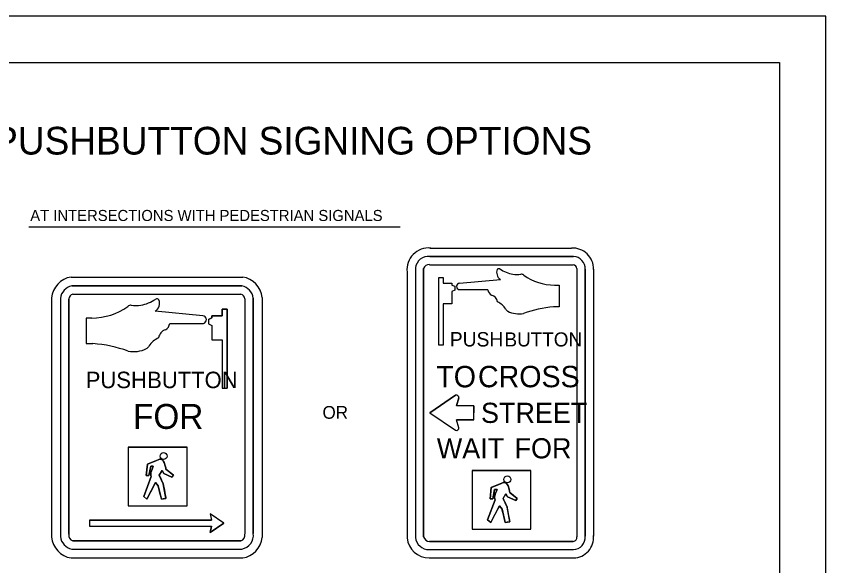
# Model space of a CAD drawing. Extents: x 1896459 to 1901611, y 1616229 to 1617416.
# Drawn here: x 1897720.6 to 1898159.1, y 1617118.8 to 1617416.5 of the extents above; entities that cross this region are included whole.
import ezdxf

# ---------------------------------------------------------------- set-up
doc = ezdxf.new("R2010")
doc.units = 0
for name, color, linetype in [('Level 24', 7, 'Continuous'), ('Level 8', 7, 'Continuous'), ('ROW_PR_Notes', 7, 'Continuous'), ('Sheets_General Details', 7, 'Continuous'), ('Signals_EX_Above Ground', 7, 'Continuous')]:
    doc.layers.add(name, color=color, linetype=linetype)

msp = doc.modelspace()

# ---------------------------------------------------------------- linework, layer by layer
at = {"layer": 'ROW_PR_Notes'}
for p, q in [((1897944.68, 1617290.9), (1898021.37, 1617290.9)), ((1897944.68, 1617286.4), (1898022.49, 1617286.4)), ((1898022.49, 1617286.4), (1897944.68, 1617286.4)), ((1897944.42, 1617281.9), (1898022.28, 1617281.9)), ((1897944.42, 1617281.9), (1898022.28, 1617281.9)), ((1897932.28, 1617277.93), (1897932.28, 1617133.9)), ((1897936.78, 1617280.12), (1897936.78, 1617134.18)), ((1897936.78, 1617280.12), (1897936.78, 1617134.18)), ((1897941.28, 1617279.75), (1897941.28, 1617134.56)), ((1897941.28, 1617134.56), (1897941.28, 1617279.75)), ((1898024.28, 1617279.75), (1898024.28, 1617134.56)), ((1898024.28, 1617279.75), (1898024.28, 1617134.56)), ((1898028.78, 1617279.44), (1898028.78, 1617134.79)), ((1898028.78, 1617134.79), (1898028.78, 1617279.44)), ((1898033.28, 1617279.38), (1898033.28, 1617134.79)), ((1897750.33, 1617275.2), (1897843.27, 1617275.2)), ((1897949.54, 1617238.3), (1897949.54, 1617274.9)), ((1897949.54, 1617274.9), (1897951.82, 1617274.9)), ((1897951.82, 1617274.9), (1897951.82, 1617271.91)), ((1897960.73, 1617271.92), (1897982.87, 1617273.96)), ((1897750.74, 1617270.4), (1897842.86, 1617270.4)), ((1897842.86, 1617270.4), (1897750.74, 1617270.4)), ((1897956.62, 1617270.87), (1897958.18, 1617270.2)), ((1897958.18, 1617268.13), (1897956.62, 1617267.45)), ((1897958.18, 1617270.2), (1897958.18, 1617268.13)), ((1897976.08, 1617268.35), (1897960.49, 1617268.35)), ((1898012.17, 1617270.77), (1898014.72, 1617270.77)), ((1897739.77, 1617263.87), (1897739.77, 1617134.41)), ((1897744.58, 1617263.65), (1897744.58, 1617134.63)), ((1897744.58, 1617263.65), (1897744.58, 1617134.63)), ((1897749.08, 1617263.37), (1897749.08, 1617135.94)), ((1897749.08, 1617135.94), (1897749.08, 1617263.37)), ((1897751.28, 1617265.9), (1897842.33, 1617265.9)), ((1897751.28, 1617265.9), (1897842.33, 1617265.9)), ((1897844.5, 1617263.48), (1897844.5, 1617136.05)), ((1897844.5, 1617263.48), (1897844.5, 1617136.05)), ((1897849, 1617263.83), (1897849, 1617136.4)), ((1897849, 1617136.4), (1897849, 1617263.83)), ((1897853.81, 1617264.1), (1897853.81, 1617134.18)), ((1897956.62, 1617267.45), (1897956.62, 1617260.76)), ((1897956.62, 1617260.76), (1897951.82, 1617260.76)), ((1897951.82, 1617260.76), (1897951.82, 1617238.3)), ((1897821.73, 1617254.26), (1897795.84, 1617256.64)), ((1897821.73, 1617254.26), (1897795.84, 1617256.64)), ((1897832.15, 1617254.25), (1897832.15, 1617257.75)), ((1897832.15, 1617257.75), (1897834.81, 1617257.75)), ((1897834.81, 1617257.75), (1897832.15, 1617257.75)), ((1897832.15, 1617257.75), (1897832.15, 1617254.25)), ((1897834.81, 1617257.75), (1897834.81, 1617214.95)), ((1897834.81, 1617214.95), (1897834.81, 1617257.75)), ((1897761.58, 1617252.92), (1897758.59, 1617252.92)), ((1897761.58, 1617252.92), (1897758.59, 1617252.92)), ((1897824.71, 1617252.24), (1897826.53, 1617253.04)), ((1897826.53, 1617253.04), (1897824.71, 1617252.24)), ((1897824.71, 1617252.24), (1897824.71, 1617249.82)), ((1897824.71, 1617252.24), (1897824.71, 1617249.82)), ((1897803.78, 1617250.09), (1897822.01, 1617250.09)), ((1897803.78, 1617250.09), (1897822.01, 1617250.09)), ((1897824.71, 1617249.82), (1897826.53, 1617249.03)), ((1897824.71, 1617249.82), (1897826.53, 1617249.03)), ((1897826.53, 1617249.03), (1897826.53, 1617241.21)), ((1897826.53, 1617249.03), (1897826.53, 1617241.21)), ((1897826.53, 1617241.21), (1897832.15, 1617241.21)), ((1897826.53, 1617241.21), (1897832.15, 1617241.21)), ((1897832.15, 1617241.21), (1897832.15, 1617214.95)), ((1897832.15, 1617241.21), (1897832.15, 1617214.95)), ((1897951.82, 1617238.3), (1897949.54, 1617238.3)), ((1897832.15, 1617214.95), (1897834.81, 1617214.95)), ((1897832.15, 1617214.95), (1897834.81, 1617214.95)), ((1897944.6, 1617201.67), (1897958.52, 1617211.15)), ((1897958.52, 1617211.15), (1897944.6, 1617201.67)), ((1897960.41, 1617209.73), (1897959.04, 1617205.42)), ((1897959.04, 1617205.42), (1897960.41, 1617209.73)), ((1897968.46, 1617205.42), (1897959.04, 1617205.42)), ((1897968.46, 1617205.42), (1897959.04, 1617205.42)), ((1897968.46, 1617205.42), (1897968.46, 1617201.67)), ((1897968.46, 1617201.67), (1897968.46, 1617205.42)), ((1897944.6, 1617201.67), (1897958.52, 1617192.2)), ((1897944.6, 1617201.67), (1897958.52, 1617192.2)), ((1897960.41, 1617193.62), (1897959.04, 1617197.93)), ((1897968.46, 1617197.93), (1897959.04, 1617197.93)), ((1897960.41, 1617193.62), (1897959.04, 1617197.93)), ((1897959.04, 1617197.93), (1897968.46, 1617197.93)), ((1897968.46, 1617197.93), (1897968.46, 1617201.67)), ((1897968.46, 1617197.93), (1897968.46, 1617201.67)), ((1897781.34, 1617183.1), (1897813.16, 1617183.1)), ((1897813.16, 1617183.1), (1897781.34, 1617183.1)), ((1897797.43, 1617176.23), (1897798.21, 1617176.52)), ((1897791.05, 1617167.65), (1897791.66, 1617173.86)), ((1897801.15, 1617173.51), (1897801.34, 1617172.92)), ((1897801.34, 1617172.92), (1897801.6, 1617171.89)), ((1897801.6, 1617171.89), (1897801.73, 1617171.09)), ((1897789.66, 1617156.41), (1897793.72, 1617167.13)), ((1897792.5, 1617167.78), (1897791.05, 1617167.65)), ((1897793.45, 1617168.62), (1897793.57, 1617169.3)), ((1897793.57, 1617169.3), (1897793.84, 1617170.24)), ((1897793.72, 1617167.13), (1897793.57, 1617167.6)), ((1897800.57, 1617168.78), (1897799.6, 1617170.52)), ((1897804.96, 1617166.9), (1897800.57, 1617168.78)), ((1897805.75, 1617167.97), (1897804.96, 1617166.9)), ((1897967.54, 1617170.46), (1897999.36, 1617170.46)), ((1897999.36, 1617170.46), (1897967.54, 1617170.46)), ((1897983.63, 1617163.59), (1897984.41, 1617163.88)), ((1897798.29, 1617158.98), (1897797.53, 1617162.19)), ((1897977.25, 1617155.01), (1897977.86, 1617161.22)), ((1897987.35, 1617160.87), (1897987.54, 1617160.28)), ((1897987.54, 1617160.28), (1897987.8, 1617159.25)), ((1897987.8, 1617159.25), (1897987.94, 1617158.45)), ((1897791.41, 1617154.87), (1897789.66, 1617156.41)), ((1897975.86, 1617143.77), (1897979.92, 1617154.49)), ((1897978.7, 1617155.14), (1897977.25, 1617155.01)), ((1897979.65, 1617155.98), (1897979.77, 1617156.66)), ((1897979.77, 1617156.66), (1897980.04, 1617157.59)), ((1897979.92, 1617154.49), (1897979.77, 1617154.96)), ((1897986.77, 1617156.14), (1897985.8, 1617157.88)), ((1897991.16, 1617154.25), (1897986.77, 1617156.14)), ((1897991.95, 1617155.32), (1897991.16, 1617154.25)), ((1897984.49, 1617146.34), (1897983.73, 1617149.54)), ((1897833.06, 1617141.9), (1897825.58, 1617146.98)), ((1897825.58, 1617146.98), (1897826.46, 1617143.54)), ((1897833.06, 1617141.9), (1897825.58, 1617146.98)), ((1897825.58, 1617146.98), (1897826.46, 1617143.54)), ((1897760.33, 1617143.54), (1897760.33, 1617140.26)), ((1897760.33, 1617143.54), (1897826.46, 1617143.54)), ((1897826.46, 1617143.54), (1897760.33, 1617143.54)), ((1897760.33, 1617143.54), (1897760.33, 1617140.26)), ((1897833.06, 1617141.9), (1897825.58, 1617136.82)), ((1897825.58, 1617136.82), (1897833.06, 1617141.9)), ((1897977.61, 1617142.23), (1897975.86, 1617143.77)), ((1897760.33, 1617140.26), (1897826.46, 1617140.26)), ((1897760.33, 1617140.26), (1897826.46, 1617140.26)), ((1897825.58, 1617136.82), (1897826.46, 1617140.26)), ((1897826.46, 1617140.26), (1897825.58, 1617136.82)), ((1897751.28, 1617132.38), (1897842.33, 1617132.38)), ((1897842.33, 1617132.38), (1897751.28, 1617132.38)), ((1897944.42, 1617132.07), (1898022.28, 1617132.07)), ((1898022.28, 1617132.07), (1897944.42, 1617132.07)), ((1897750.74, 1617127.88), (1897842.86, 1617127.88)), ((1897750.74, 1617127.88), (1897842.86, 1617127.88)), ((1897944.28, 1617127.57), (1898022.4, 1617127.57)), ((1897944.28, 1617127.57), (1898022.4, 1617127.57)), ((1897750.33, 1617123.07), (1897843.27, 1617123.07)), ((1897944.26, 1617123.07), (1898022.49, 1617123.07))]:
    msp.add_line(p, q, dxfattribs=at)
for points in [[(1897951.82, 1617271.91), (1897956.62, 1617271.91), (1897956.62, 1617270.87)], [(1898014.72, 1617270.77), (1898014.72, 1617259.02), (1898011.65, 1617259.02)], [(1897758.59, 1617252.92), (1897758.59, 1617239.17), (1897762.19, 1617239.17)], [(1897758.59, 1617252.92), (1897758.59, 1617239.17), (1897762.19, 1617239.17)], [(1897826.53, 1617253.04), (1897826.53, 1617254.25), (1897832.15, 1617254.25)], [(1897832.15, 1617254.25), (1897826.53, 1617254.25), (1897826.53, 1617253.04)], [(1897781.34, 1617183.1), (1897781.34, 1617151.28), (1897813.16, 1617151.28), (1897813.16, 1617183.1)], [(1897781.34, 1617183.1), (1897781.34, 1617151.28), (1897813.16, 1617151.28), (1897813.16, 1617183.1)], [(1897791.66, 1617173.86), (1897794.33, 1617174.96), (1897797.43, 1617176.23)], [(1897798.21, 1617176.52), (1897798.95, 1617176.53), (1897799.35, 1617176.43)], [(1897799.35, 1617176.43), (1897799.71, 1617176.23), (1897799.98, 1617175.96), (1897800.45, 1617175.35), (1897800.78, 1617174.7), (1897800.97, 1617174.15), (1897801.15, 1617173.51)], [(1897793.84, 1617170.24), (1897794.2, 1617171.22), (1897794.63, 1617172.18), (1897794.88, 1617172.76), (1897793.51, 1617172.74), (1897793.17, 1617171.09), (1897793.03, 1617170.37)], [(1897793.03, 1617170.37), (1897792.78, 1617169.12), (1897792.5, 1617167.78)], [(1897793.57, 1617167.6), (1897793.47, 1617168.24), (1897793.45, 1617168.62)], [(1897799.6, 1617170.52), (1897798.86, 1617169.27), (1897798.06, 1617167.9), (1897798.47, 1617167.03), (1897799.32, 1617165.21), (1897800.23, 1617163.26)], [(1897801.73, 1617171.09), (1897803.04, 1617170.07), (1897805.75, 1617167.97)], [(1897967.54, 1617170.46), (1897967.54, 1617138.64), (1897999.36, 1617138.64), (1897999.36, 1617170.46)], [(1897967.54, 1617170.46), (1897967.54, 1617138.64), (1897999.36, 1617138.64), (1897999.36, 1617170.46)], [(1897797.53, 1617162.19), (1897796.12, 1617163.94), (1897795.15, 1617162.05), (1897791.62, 1617155.22), (1897791.41, 1617154.87)], [(1897800.23, 1617163.26), (1897800.27, 1617163.09), (1897800.29, 1617162.96)], [(1897800.29, 1617162.96), (1897800.34, 1617162.66), (1897800.47, 1617161.99)], [(1897977.86, 1617161.22), (1897980.53, 1617162.32), (1897983.63, 1617163.59)], [(1897984.41, 1617163.88), (1897985.15, 1617163.89), (1897985.55, 1617163.79)], [(1897985.55, 1617163.79), (1897985.91, 1617163.59), (1897986.18, 1617163.32), (1897986.65, 1617162.71), (1897986.98, 1617162.06), (1897987.17, 1617161.51), (1897987.35, 1617160.87)], [(1897800.47, 1617161.99), (1897800.48, 1617161.92), (1897800.68, 1617160.88), (1897801.07, 1617158.78), (1897801.37, 1617157.19), (1897801.59, 1617156.06), (1897801.7, 1617155.35), (1897800.28, 1617155.05), (1897799.26, 1617154.87), (1897798.86, 1617156.51), (1897798.48, 1617158.13), (1897798.29, 1617158.98)], [(1897980.04, 1617157.59), (1897980.4, 1617158.58), (1897980.83, 1617159.54), (1897981.09, 1617160.12), (1897979.72, 1617160.1), (1897979.38, 1617158.44), (1897979.23, 1617157.73)], [(1897987.94, 1617158.45), (1897989.24, 1617157.43), (1897991.95, 1617155.32)], [(1897979.23, 1617157.73), (1897978.98, 1617156.47), (1897978.7, 1617155.14)], [(1897979.77, 1617154.96), (1897979.67, 1617155.59), (1897979.65, 1617155.98)], [(1897985.8, 1617157.88), (1897985.07, 1617156.63), (1897984.26, 1617155.26), (1897984.67, 1617154.39), (1897985.52, 1617152.57), (1897986.43, 1617150.61)], [(1897983.73, 1617149.54), (1897982.32, 1617151.3), (1897981.36, 1617149.41), (1897977.82, 1617142.58), (1897977.61, 1617142.23)], [(1897986.43, 1617150.61), (1897986.47, 1617150.45), (1897986.49, 1617150.32)], [(1897986.49, 1617150.32), (1897986.54, 1617150.01), (1897986.67, 1617149.35)], [(1897986.67, 1617149.35), (1897986.68, 1617149.28), (1897986.89, 1617148.24), (1897987.27, 1617146.14), (1897987.57, 1617144.55), (1897987.79, 1617143.41), (1897987.9, 1617142.71), (1897986.48, 1617142.41), (1897985.47, 1617142.23), (1897985.06, 1617143.87), (1897984.68, 1617145.49), (1897984.49, 1617146.34)]]:
    msp.add_lwpolyline(points, dxfattribs=at)
for points in [[(1897791.05, 1617167.65), (1897792.5, 1617167.78), (1897793.51, 1617172.74), (1897794.88, 1617172.76), (1897794.2, 1617171.22), (1897793.84, 1617170.24), (1897793.57, 1617169.3), (1897793.45, 1617168.62), (1897793.57, 1617167.6), (1897793.72, 1617167.13), (1897789.66, 1617156.41), (1897791.41, 1617154.87), (1897796.12, 1617163.94), (1897797.53, 1617162.19), (1897799.26, 1617154.87), (1897801.7, 1617155.35), (1897800.23, 1617163.26), (1897798.06, 1617167.9), (1897799.6, 1617170.52), (1897800.57, 1617168.78), (1897804.96, 1617166.9), (1897805.75, 1617167.97), (1897801.73, 1617171.09), (1897801.6, 1617171.89), (1897801.34, 1617172.92), (1897801.15, 1617173.51), (1897800.97, 1617174.15), (1897800.78, 1617174.7), (1897800.45, 1617175.35), (1897799.98, 1617175.96), (1897799.71, 1617176.23), (1897799.35, 1617176.43), (1897798.95, 1617176.53), (1897798.21, 1617176.52), (1897797.43, 1617176.23), (1897791.66, 1617173.86)], [(1897977.25, 1617155.01), (1897978.7, 1617155.14), (1897979.72, 1617160.1), (1897981.09, 1617160.12), (1897980.4, 1617158.58), (1897980.04, 1617157.59), (1897979.77, 1617156.66), (1897979.65, 1617155.98), (1897979.77, 1617154.96), (1897979.92, 1617154.49), (1897975.86, 1617143.77), (1897977.61, 1617142.23), (1897982.32, 1617151.3), (1897983.73, 1617149.54), (1897985.47, 1617142.23), (1897987.9, 1617142.71), (1897986.43, 1617150.61), (1897984.26, 1617155.26), (1897985.8, 1617157.88), (1897986.77, 1617156.14), (1897991.16, 1617154.25), (1897991.95, 1617155.32), (1897987.94, 1617158.45), (1897987.8, 1617159.25), (1897987.54, 1617160.28), (1897987.35, 1617160.87), (1897987.17, 1617161.51), (1897986.98, 1617162.06), (1897986.65, 1617162.71), (1897986.18, 1617163.32), (1897985.91, 1617163.59), (1897985.55, 1617163.79), (1897985.15, 1617163.89), (1897984.41, 1617163.88), (1897983.63, 1617163.59), (1897977.86, 1617161.22)]]:
    msp.add_lwpolyline(points, close=True, dxfattribs=at)
for centre in [(1897800.41, 1617178.26), (1897986.61, 1617165.62)]:
    msp.add_circle(centre, 1.88, dxfattribs=at)
for centre, radius, start, end in [((1897943.99, 1617279.16), 11.78, 84.586, 185.9926), ((1898022, 1617279.63), 11.28, 358.7025, 93.208), ((1897943.99, 1617279.16), 7.28, 84.586, 172.3742), ((1897943.99, 1617279.16), 7.28, 84.586, 172.3742), ((1898022, 1617279.63), 6.78, 358.3264, 85.8621), ((1898022, 1617279.63), 6.78, 358.3264, 85.8621), ((1897943.99, 1617279.16), 2.78, 81.2299, 167.6396), ((1897943.99, 1617279.16), 2.78, 81.2299, 167.6396), ((1898022, 1617279.63), 2.28, 2.8853, 82.8635), ((1898022, 1617279.63), 2.28, 2.8853, 82.8635), ((1897985.22, 1617277.71), 4.43, 158.6143, 237.9265), ((1897982, 1617278.57), 1.17, 60.1432, 139.8831), ((1897992.92, 1617295.1), 18.64, 236.3211, 259.5618), ((1897991.71, 1617290.6), 14, 261.0873, 278.9127), ((1897994.08, 1617274.73), 2.04, 47.7167, 95.5991), ((1897752.23, 1617262.85), 12.49, 98.74, 175.3325), ((1897841.38, 1617262.85), 12.49, 5.6984, 81.26), ((1898012.72, 1617300.76), 29.99, 234.8361, 268.9413), ((1897752.23, 1617262.85), 7.69, 101.1488, 174.0488), ((1897752.23, 1617262.85), 7.69, 101.1488, 174.0488), ((1897841.38, 1617262.85), 7.69, 7.2664, 78.8512), ((1897841.38, 1617262.85), 7.69, 7.2664, 78.8512), ((1897960.92, 1617270.11), 1.81, 95.9265, 256.3937), ((1897979.98, 1617268.85), 3.93, 187.3676, 240.2754), ((1897752.23, 1617262.85), 3.19, 107.3522, 170.7522), ((1897752.23, 1617262.85), 3.19, 107.3522, 170.7522), ((1897796.86, 1617262.03), 1.37, 40.1169, 119.8568), ((1897796.86, 1617262.03), 1.37, 40.1169, 119.8568), ((1897841.38, 1617262.85), 3.19, 11.295, 72.6478), ((1897841.38, 1617262.85), 3.19, 11.295, 72.6478), ((1897976.63, 1617260.94), 4.72, 9.6191, 72.6554), ((1897760.93, 1617287.98), 35.07, 271.0587, 305.1639), ((1897760.93, 1617287.98), 35.07, 271.0587, 305.1639), ((1897782.73, 1617257.55), 2.39, 84.4009, 132.2833), ((1897782.73, 1617257.55), 2.39, 84.4009, 132.2833), ((1897785.5, 1617276.1), 16.37, 261.0873, 278.9127), ((1897785.5, 1617276.1), 16.37, 261.0873, 278.9127), ((1897784.09, 1617281.36), 21.8, 280.4382, 303.6789), ((1897784.09, 1617281.36), 21.8, 280.4382, 303.6789), ((1897793.09, 1617261.03), 5.18, 302.0735, 21.3857), ((1897793.09, 1617261.03), 5.18, 302.0735, 21.3857), ((1897975.9, 1617250.99), 12.01, 34.9045, 63.415), ((1898016.39, 1617196.67), 62.53, 94.3476, 109.7287), ((1897988.02, 1617258.93), 2.51, 205.2403, 242.0015), ((1897992.74, 1617268.05), 12.78, 242.506, 281.4571), ((1897821.51, 1617252.15), 2.12, 283.6063, 84.0735), ((1897821.51, 1617252.15), 2.12, 283.6063, 84.0735), ((1897803.14, 1617241.43), 5.51, 107.3446, 170.3809), ((1897803.14, 1617241.43), 5.51, 107.3446, 170.3809), ((1897799.22, 1617250.68), 4.59, 299.7246, 352.6324), ((1897799.22, 1617250.68), 4.59, 299.7246, 352.6324), ((1897803.99, 1617229.78), 14.05, 116.585, 145.0955), ((1897803.99, 1617229.78), 14.05, 116.585, 145.0955), ((1897756.64, 1617166.26), 73.12, 70.2713, 85.6524), ((1897756.64, 1617166.26), 73.12, 70.2713, 85.6524), ((1897789.81, 1617239.07), 2.94, 297.9985, 334.7597), ((1897789.81, 1617239.07), 2.94, 297.9985, 334.7597), ((1897784.3, 1617249.73), 14.94, 258.5429, 297.494), ((1897784.3, 1617249.73), 14.94, 258.5429, 297.494), ((1897958.91, 1617209.7), 1.5, 1.0577, 104.8282), ((1897958.91, 1617209.7), 1.5, 1.0577, 104.8282), ((1897958.91, 1617193.65), 1.5, 255.1718, 358.9423), ((1897958.91, 1617193.65), 1.5, 255.1718, 358.9423), ((1897841.38, 1617135.42), 7.69, 281.1488, 7.2664), ((1897841.38, 1617135.42), 7.69, 281.1488, 7.2664), ((1897752.23, 1617135.42), 12.49, 184.6675, 261.26), ((1897752.23, 1617135.42), 7.69, 185.9512, 258.8512), ((1897752.23, 1617135.42), 7.69, 185.9512, 258.8512), ((1897752.23, 1617135.42), 3.19, 170.7522, 252.6478), ((1897752.23, 1617135.42), 3.19, 170.7522, 252.6478), ((1897841.38, 1617135.42), 3.19, 287.3522, 11.295), ((1897841.38, 1617135.42), 3.19, 287.3522, 11.295), ((1897841.38, 1617135.42), 12.49, 278.74, 354.3016), ((1897944.37, 1617135.23), 12.16, 186.2596, 269.5161), ((1897944.37, 1617135.23), 7.66, 187.8899, 269.3902), ((1897944.37, 1617135.23), 7.66, 187.8899, 269.3902), ((1897944.37, 1617135.23), 3.16, 192.3033, 270.9498), ((1897944.37, 1617135.23), 3.16, 192.3033, 270.9498), ((1898022.13, 1617134.25), 2.18, 274.1811, 8.2294), ((1898022.13, 1617134.25), 2.18, 274.1811, 8.2294), ((1898022.13, 1617134.25), 6.68, 272.387, 4.6961), ((1898022.13, 1617134.25), 6.68, 272.387, 4.6961), ((1898022.13, 1617134.25), 11.18, 271.8448, 4.6961)]:
    msp.add_arc(centre, radius, start, end, dxfattribs=at)
at = {"layer": 'Sheets_General Details'}
for p, q in [((1898159.07, 1617416.47), (1896459.07, 1617416.47)), ((1898159.07, 1616316.47), (1898159.07, 1617416.47)), ((1897727.4, 1617302.45), (1897928.52, 1617302.45))]:
    msp.add_line(p, q, dxfattribs=at)
for points in [[(1896459.07, 1616316.47), (1898159.07, 1616316.47), (1898159.07, 1617416.47), (1896459.07, 1617416.47)], [(1896559.07, 1617391.47), (1898134.07, 1617391.47), (1898134.07, 1616341.47), (1896559.07, 1616341.47)], [(1896559.07, 1617391.46), (1898134.07, 1617391.46), (1898134.07, 1616391.47), (1896559.07, 1616391.47)]]:
    msp.add_lwpolyline(points, close=True, dxfattribs=at)
at = {"layer": 'Signals_EX_Above Ground'}
for points in [[(1897791.66, 1617173.88), (1897796.64, 1617175.9), (1897797.43, 1617176.23), (1897798.21, 1617176.52), (1897798.95, 1617176.53), (1897799.35, 1617176.43), (1897799.71, 1617176.23), (1897799.98, 1617175.96), (1897800.45, 1617175.35), (1897800.78, 1617174.7), (1897800.97, 1617174.15), (1897801.15, 1617173.51), (1897801.34, 1617172.92), (1897801.6, 1617171.89), (1897801.73, 1617171.09), (1897802.19, 1617170.72), (1897803.04, 1617170.07), (1897803.75, 1617169.49), (1897804.43, 1617168.97), (1897805.21, 1617168.37), (1897805.75, 1617167.97), (1897804.96, 1617166.9), (1897800.57, 1617168.78), (1897799.6, 1617170.52), (1897798.86, 1617169.27), (1897798.06, 1617167.9), (1897798.46, 1617167.03), (1897798.9, 1617166.08), (1897799.31, 1617165.21), (1897799.65, 1617164.47), (1897799.9, 1617163.92), (1897800.23, 1617163.26), (1897800.27, 1617163.09), (1897800.33, 1617162.65), (1897800.48, 1617161.92), (1897800.68, 1617160.88), (1897801.07, 1617158.78), (1897801.37, 1617157.19), (1897801.59, 1617156.06), (1897801.7, 1617155.35), (1897800.28, 1617155.05), (1897799.26, 1617154.87), (1897798.86, 1617156.51), (1897798.48, 1617158.13), (1897798, 1617160.28), (1897797.67, 1617161.65), (1897797.53, 1617162.19), (1897796.12, 1617163.94), (1897795.15, 1617162.05), (1897791.62, 1617155.22), (1897791.41, 1617154.87), (1897789.66, 1617156.41), (1897793.72, 1617167.13), (1897793.57, 1617167.6), (1897793.47, 1617168.24), (1897793.45, 1617168.62), (1897793.57, 1617169.3), (1897793.84, 1617170.24), (1897794.2, 1617171.22), (1897794.64, 1617172.18), (1897794.88, 1617172.76), (1897793.51, 1617172.74), (1897793.17, 1617171.09), (1897792.78, 1617169.12), (1897792.5, 1617167.78), (1897791.05, 1617167.65), (1897791.66, 1617173.86)], [(1897977.86, 1617161.24), (1897982.84, 1617163.26), (1897983.63, 1617163.59), (1897984.41, 1617163.88), (1897985.15, 1617163.89), (1897985.55, 1617163.79), (1897985.91, 1617163.59), (1897986.18, 1617163.32), (1897986.65, 1617162.71), (1897986.98, 1617162.06), (1897987.17, 1617161.51), (1897987.35, 1617160.87), (1897987.54, 1617160.28), (1897987.8, 1617159.25), (1897987.94, 1617158.45), (1897988.39, 1617158.08), (1897989.24, 1617157.43), (1897989.96, 1617156.85), (1897990.63, 1617156.33), (1897991.41, 1617155.73), (1897991.95, 1617155.32), (1897991.16, 1617154.25), (1897986.77, 1617156.14), (1897985.8, 1617157.88), (1897985.06, 1617156.63), (1897984.26, 1617155.26), (1897984.66, 1617154.39), (1897985.1, 1617153.43), (1897985.52, 1617152.57), (1897985.85, 1617151.83), (1897986.1, 1617151.28), (1897986.43, 1617150.61), (1897986.47, 1617150.45), (1897986.54, 1617150.01), (1897986.68, 1617149.28), (1897986.89, 1617148.24), (1897987.27, 1617146.14), (1897987.57, 1617144.55), (1897987.79, 1617143.41), (1897987.9, 1617142.71), (1897986.48, 1617142.41), (1897985.47, 1617142.23), (1897985.06, 1617143.87), (1897984.68, 1617145.49), (1897984.2, 1617147.64), (1897983.88, 1617149.01), (1897983.73, 1617149.54), (1897982.32, 1617151.3), (1897981.36, 1617149.41), (1897977.82, 1617142.58), (1897977.61, 1617142.23), (1897975.86, 1617143.77), (1897979.92, 1617154.49), (1897979.77, 1617154.96), (1897979.67, 1617155.59), (1897979.65, 1617155.98), (1897979.77, 1617156.66), (1897980.04, 1617157.59), (1897980.4, 1617158.58), (1897980.84, 1617159.53), (1897981.09, 1617160.12), (1897979.72, 1617160.1), (1897979.37, 1617158.45), (1897978.98, 1617156.47), (1897978.7, 1617155.14), (1897977.25, 1617155.01), (1897977.86, 1617161.22)]]:
    msp.add_lwpolyline(points, dxfattribs=at)
for centre in [(1897800.41, 1617178.26), (1897986.61, 1617165.62)]:
    msp.add_circle(centre, 1.88, dxfattribs=at)

# ---------------------------------------------------------------- texts
at = {"layer": 'Level 24'}
msp.add_text('APS PUSHBUTTON SIGNING OPTIONS', height=15, dxfattribs=at).set_placement((1897662.42, 1617341.55))
at = {"layer": 'Level 8'}
for s, height, p in [('AT INTERSECTIONS WITH PEDESTRIAN SIGNALS', 6, (1897728.23, 1617305.55)), ('OR', 6.901, (1897886.49, 1617198.45))]:
    msp.add_text(s, height=height, dxfattribs=at).set_placement(p)
at = {"layer": 'ROW_PR_Notes'}
for s, height, p in [('PUSH', 7.802, (1897955.44, 1617237.59)), ('BUTTON', 7.643, (1897985.07, 1617237.6)), ('PUSH', 8.91, (1897758.28, 1617215.04)), ('BUTTON', 8.91, (1897791.54, 1617215.04)), ('TO', 11.577, (1897948.12, 1617215.48)), ('CROSS', 11.577, (1897970.7, 1617215.52)), ('FOR', 13.487, (1897783.91, 1617192.97)), ('STREET', 10.92, (1897972.33, 1617196.2)), ('WAIT', 10.92, (1897948.4, 1617176.98)), ('FOR', 10.92, (1897990.51, 1617177))]:
    msp.add_text(s, height=height, dxfattribs=at).set_placement(p)

doc.saveas('drawing.dxf')
